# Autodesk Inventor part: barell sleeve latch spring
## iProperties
Created: 2006-04
Part Number: barell sleeve latch spring
Document SubType Name: Modeling
Designer: Калинин
Author: Калинин
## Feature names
1. Пружина1
